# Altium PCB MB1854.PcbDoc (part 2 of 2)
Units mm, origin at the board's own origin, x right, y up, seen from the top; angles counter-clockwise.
Board outline 50.11 x 30.1 mm, 4 copper layers (Top Layer, Signal Layer 1, Signal Layer 2, Bottom Layer), stack 1.556 mm thick; 50 components, 31 nets, 194 pads, 158 vias.
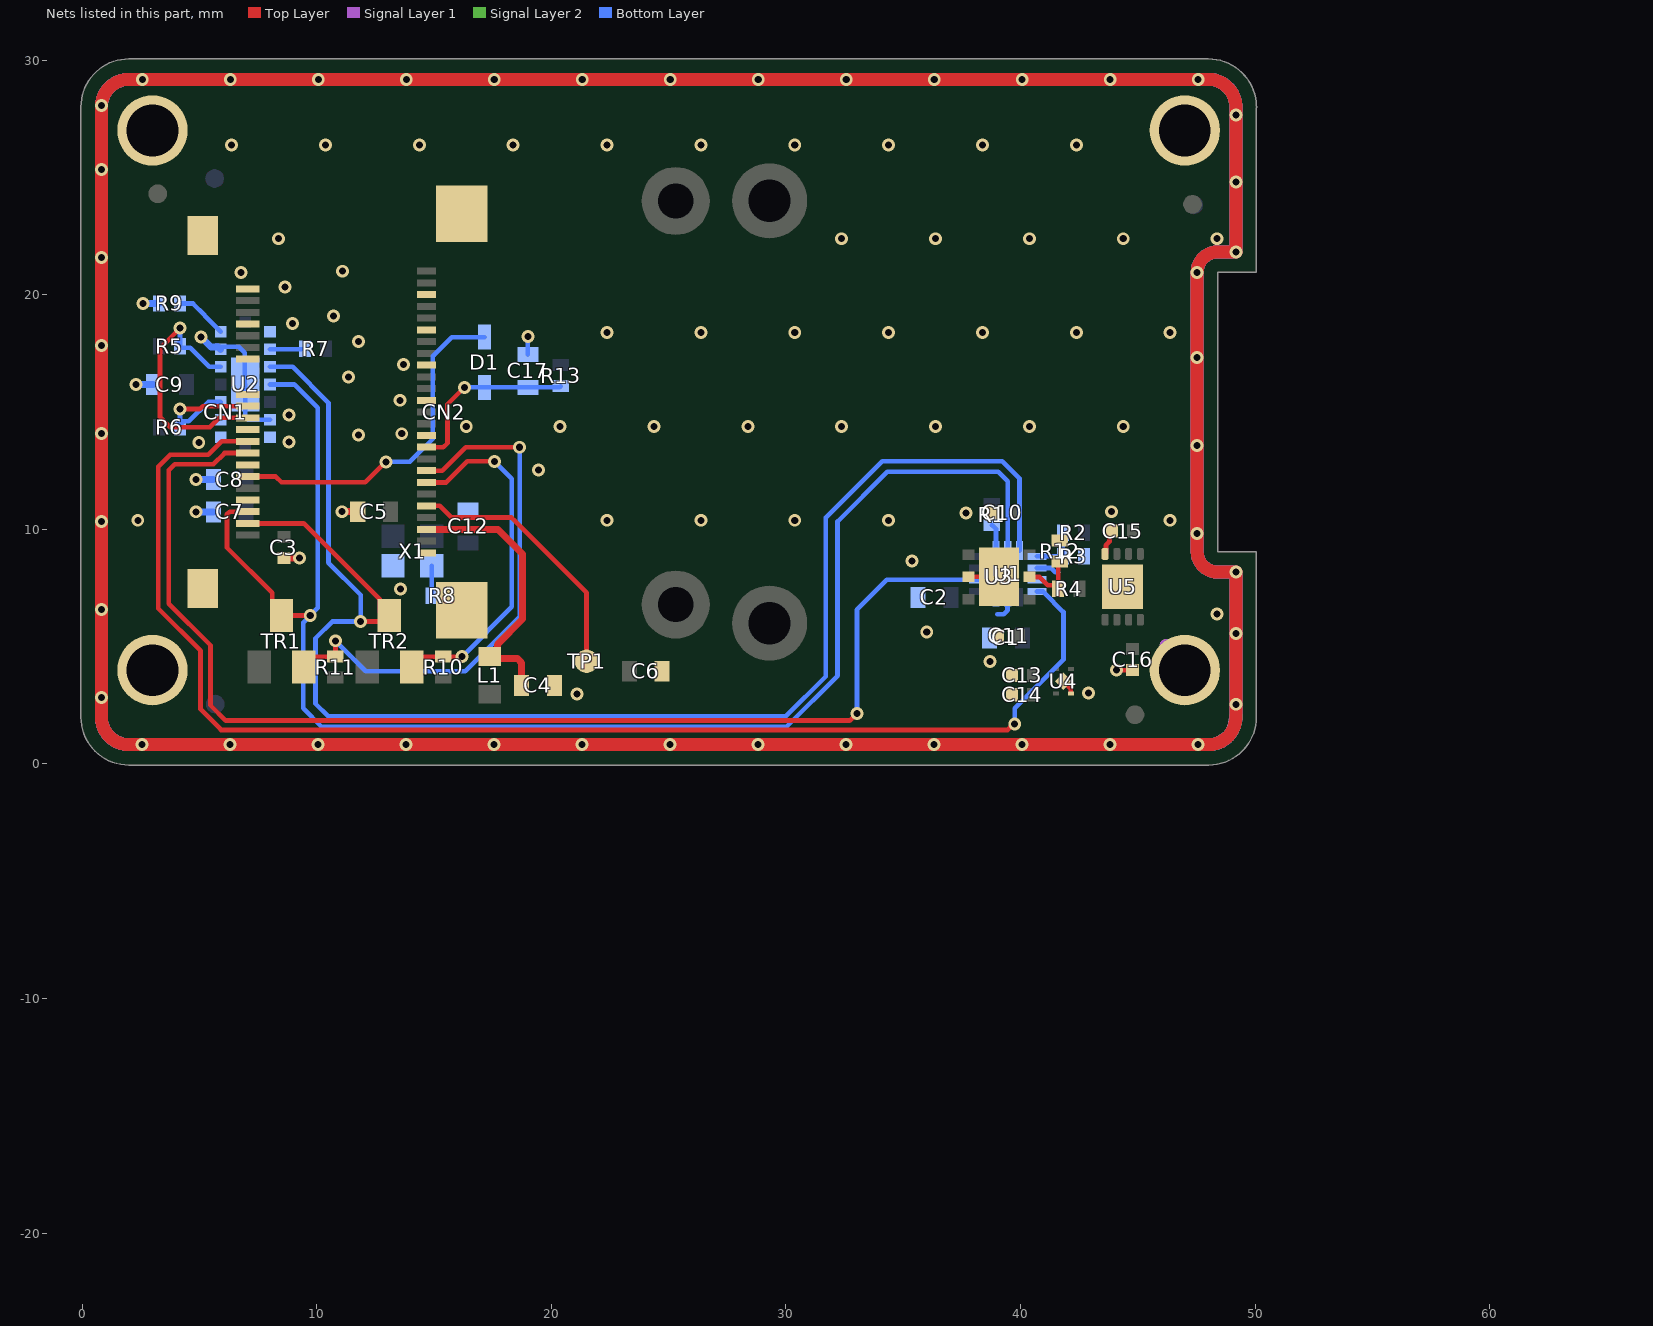
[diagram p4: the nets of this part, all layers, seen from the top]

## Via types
v1: diameter 0.55, hole 0.3, Top Layer to Bottom Layer, tented both sides, 158 vias

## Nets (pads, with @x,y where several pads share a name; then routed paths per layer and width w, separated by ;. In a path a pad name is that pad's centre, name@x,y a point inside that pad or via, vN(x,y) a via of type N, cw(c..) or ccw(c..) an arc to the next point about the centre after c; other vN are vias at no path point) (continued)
GND: C1.1 C2.1 C3.1 C4.2 C5.2 C6.2 C7.1 C8.1 C9.1 C10.1 C11.1 C12.1 C13.1 C14.1 C15.1 C16.1 C17.2 CN1.1 CN1.4 CN1.7 CN1.10 CN1.13 CN1.16 CN1.19 CN1.S1 CN1.S2 CN2.1 CN2.11 CN2.14 CN2.17 CN2.20 CN2.23 CN2.S1 CN2.S2 pad.1@3,4 pad.1@3,27 pad.1@47,4 pad.1@47,27 R3.1 R9.1 R12.1 U1.2 U1.3 U1.6 U1.7 U2.A2 U2.A6 U2.A7 U2.B4 U2.C1 U2.C6 U2.C7 U3.2 U3.EP U4.2 U4.5 U5.4 U5.9 X1.2 | length 635.1
  Top Layer w0.2: U3.2@37.778,7.975 U3.EP@39.078,7.975 ; U4.5@41.828,3.525 42.142,3.21 U4.2@42.142,3.05 ; U5.4@43.603,8.95 43.638,8.985 43.638,9.326 43.789,9.477 43.789,9.814 C15.1@43.9,9.925 ; v1(44.088,4) C16.1@44.763,4
  Top Layer w0.3: C3.1@8.6,8.775 v1@9.225,8.775 ; v1(11.075,10.75) C5.2@11.75,10.75
  Top Layer w0.55: v1(0.825,28.071) 0.825,25.342 0.825,21.592 0.825,17.842 v1(0.826,14.091) v1(0.826,10.341) v1(0.826,6.591) 0.826,3.667 v1(0.826,2.841) 0.827,2.014 cw(c-0.048,2.014) 0.825,1.968 ccw(c1.375,1.94) 0.825,1.939 ccw(c1.375,1.938) 0.835,1.831 0.859,1.71 ccw(c1.399,1.818) 0.89,1.607 0.938,1.493 ccw(c1.446,1.704) 0.988,1.398 1.057,1.296 ccw(c1.514,1.601) 1.124,1.214 1.212,1.125 ccw(c1.601,1.514) 1.296,1.057 1.443,0.959 1.607,0.891 ccw(c1.817,1.399) 1.709,0.86 1.831,0.835 ccw(c1.938,1.375) 1.938,0.825 v1(2.558,0.825) v1(6.308,0.825) v1(10.058,0.825) v1(13.809,0.825) v1(17.559,0.825) v1(21.309,0.825) v1(25.06,0.825) v1(28.81,0.825) v1(32.56,0.825) v1(36.31,0.825) v1(40.061,0.825) v1(43.811,0.825) v1(47.561,0.825) 48.014,0.825 ccw(c48.014,1.375) 48.02,0.825 48.074,0.825 ccw(c48.068,1.375) 48.18,0.837 48.301,0.862 ccw(c48.188,1.4) 48.403,0.894 48.515,0.942 ccw(c48.3,1.448) 48.609,0.993 48.71,1.061 ccw(c48.402,1.517) 48.792,1.13 48.879,1.217 ccw(c48.488,1.604) 48.947,1.301 49.014,1.402 ccw(c48.555,1.706) 49.064,1.496 49.11,1.609 ; v1@0.827,28.071 cw(c1.377,28.071) 0.837,28.179 0.859,28.29 cw(c1.399,28.182) 0.89,28.393 0.938,28.507 cw(c1.446,28.296) 0.988,28.602 1.057,28.705 cw(c1.514,28.399) 1.125,28.788 1.212,28.874 cw(c1.601,28.486) 1.296,28.943 1.399,29.012 cw(c1.704,28.554) 1.494,29.063 1.607,29.109 cw(c1.818,28.601) 1.711,29.141 1.832,29.165 cw(c1.938,28.625) 1.938,29.175 v1(2.567,29.175) v1(6.318,29.175) v1(10.068,29.175) v1(13.818,29.175) v1(17.568,29.175) v1(21.319,29.175) v1(25.069,29.175) v1(28.819,29.175) v1(32.57,29.175) v1(36.32,29.175) v1(40.07,29.175) v1(43.82,29.175) v1(47.571,29.175) 47.737,29.175 48,29.175 48.061,29.175 cw(c48.061,28.625) 48.168,29.165 48.286,29.142 cw(c48.181,28.602) 48.389,29.111 48.5,29.065 cw(c48.293,28.556) 48.597,29.014 48.697,28.948 cw(c48.395,28.489) 48.782,28.88 48.867,28.796 cw(c48.482,28.403) 48.937,28.712 49.004,28.614 cw(c48.551,28.302) 49.057,28.518 49.104,28.409 cw(c48.599,28.19) 49.137,28.305 49.162,28.187 cw(c48.624,28.071) 49.174,28.079 49.175,28.019 ccw(c50.05,28.034) 49.177,27.98 cw(c48.628,27.946) 49.178,27.944 v1(49.178,27.661) 49.178,27.378 v1(49.175,24.8) v1(49.176,21.825) 48.4,21.825 ccw(c48.4,20.95) v1(47.525,20.95) v1(47.525,17.322) v1(47.525,13.571) v1(47.525,9.821) 47.525,9.05 ccw(c48.4,9.05) 48.4,8.175 v1(49.175,8.175) v1(49.175,5.562) v1(49.175,2.543) 49.175,1.92 ; 49.11,1.609 ccw(c48.602,1.819) 49.142,1.714 49.165,1.831 ccw(c48.626,1.941) 49.175,1.919
  Signal Layer 1 w0.55: pad.1@46.193,3.16 pad.1@46.193,5.046 ; 49.175,26.922 49.175,28.049 49.174,28.079 ccw(c48.624,28.071) 49.162,28.188 49.137,28.305 ccw(c48.599,28.19) 49.104,28.409 49.057,28.518 ccw(c48.551,28.302) 49.004,28.614 48.937,28.712 ccw(c48.482,28.403) 48.867,28.796 48.782,28.88 ccw(c48.395,28.489) 48.697,28.948 48.597,29.014 ccw(c48.293,28.556) 48.501,29.065 48.39,29.111 ccw(c48.181,28.602) 48.285,29.142 48.169,29.165 ccw(c48.062,28.625) 48.077,29.175 ccw(c48.048,28.049) 48.048,29.175 v1(47.571,29.175) v1(43.82,29.175) v1(40.07,29.175) v1(36.32,29.175) v1(32.57,29.175) v1(28.819,29.175) v1(25.069,29.175) v1(21.319,29.175) v1(17.568,29.175) v1(13.818,29.175) v1(10.068,29.175) v1(6.318,29.175) v1(2.567,29.175) 1.938,29.175 ccw(c1.938,28.625) 1.832,29.165 1.711,29.141 ccw(c1.818,28.601) 1.607,29.109 1.494,29.063 ccw(c1.704,28.554) 1.398,29.011 1.267,28.924 ccw(c1.571,28.466) 1.265,28.923 1.251,28.913 1.125,28.788 ccw(c1.514,28.399) 1.057,28.705 0.988,28.602 ccw(c1.446,28.296) 0.938,28.507 0.89,28.393 ccw(c1.399,28.182) 0.859,28.29 0.837,28.178 ccw(c1.376,28.071) 0.826,28.071 v1(0.826,25.342) v1(0.826,21.592) v1(0.826,17.842) v1(0.826,14.091) v1(0.826,10.341) v1(0.826,6.591) v1(0.826,2.841) 0.827,2.014 cw(c-0.048,2.014) 0.825,1.968 ccw(c1.375,1.94) 0.825,1.94 0.825,1.884 0.859,1.71 ccw(c1.399,1.818) 0.89,1.607 0.938,1.493 ccw(c1.446,1.704) 0.988,1.398 1.057,1.296 ccw(c1.514,1.601) 1.125,1.213 1.212,1.125 ccw(c1.601,1.514) 1.296,1.057 1.398,0.989 ccw(c1.704,1.446) 1.493,0.938 1.607,0.891 ccw(c1.817,1.399) 1.709,0.86 1.831,0.835 ccw(c1.938,1.375) 1.938,0.825 v1(2.558,0.825) 3.496,0.825 48.016,0.825 ccw(c48.014,1.375) 48.02,0.825 48.074,0.825 ccw(c48.068,1.375) 48.18,0.837 48.301,0.862 ccw(c48.188,1.4) 48.403,0.894 48.515,0.942 ccw(c48.3,1.448) 48.609,0.993 48.71,1.061 ccw(c48.402,1.517) 48.792,1.13 48.879,1.217 ccw(c48.488,1.604) 48.946,1.3 48.984,1.357 ccw(c48.526,1.661) 49.043,1.473 ccw(c46.944,2.231) 49.175,2.231 v1(49.175,2.543) v1(49.175,5.562) v1(49.175,8.175) 48.4,8.175 cw(c48.4,9.05) 47.525,9.05 v1(47.525,9.821) v1(47.525,13.571) v1(47.525,17.322) v1(47.525,20.95) cw(c48.4,20.95) 48.4,21.825 v1(49.176,21.825) 49.176,26.922
  Signal Layer 2 w0.55: 0.825,1.968 ccw(c1.969,1.968) 0.828,1.894 ccw(c1.377,1.928) 0.837,1.82 0.859,1.709 ccw(c1.399,1.818) 0.89,1.607 0.938,1.493 ccw(c1.446,1.704) 0.988,1.398 1.057,1.296 ccw(c1.514,1.601) 1.125,1.213 1.212,1.125 ccw(c1.601,1.514) 1.296,1.057 1.398,0.989 ccw(c1.704,1.446) 1.493,0.938 1.607,0.891 ccw(c1.817,1.399) 1.71,0.859 1.824,0.836 ccw(c1.932,1.376) 1.895,0.827 ccw(c1.969,1.968) 1.969,0.825 v1(2.558,0.825) v1(6.308,0.825) v1(10.058,0.825) v1(13.809,0.825) v1(17.559,0.825) v1(21.309,0.825) v1(25.06,0.825) v1(28.81,0.825) v1(32.56,0.825) v1(36.31,0.825) v1(40.061,0.825) v1(43.811,0.825) v1(47.561,0.825) 48.014,0.825 ccw(c48.014,1.375) 48.02,0.825 48.074,0.825 ccw(c48.068,1.375) 48.18,0.837 48.301,0.862 ccw(c48.188,1.4) 48.403,0.894 48.515,0.942 ccw(c48.3,1.448) 48.609,0.993 48.71,1.061 ccw(c48.402,1.517) 48.792,1.13 48.879,1.217 ccw(c48.488,1.604) 48.946,1.3 48.985,1.359 49.014,1.402 ccw(c48.555,1.706) 49.064,1.497 49.11,1.609 ccw(c48.602,1.819) 49.141,1.712 49.165,1.831 ccw(c48.625,1.939) 49.175,1.939 v1(49.175,2.543) v1(49.175,5.562) v1(49.175,8.175) 48.4,8.175 cw(c48.4,9.05) 47.525,9.05 v1(47.525,9.821) v1(47.525,13.571) v1(47.525,17.322) v1(47.525,20.95) cw(c48.4,20.95) 48.4,21.825 v1(49.176,21.825) v1(49.175,24.8) 49.177,26.089 49.177,27.956 ccw(c48.627,27.957) 49.176,27.987 cw(c50.05,28.034) 49.175,28.019 49.174,28.079 ccw(c48.624,28.071) 49.162,28.187 49.137,28.305 ccw(c48.599,28.19) 49.104,28.409 49.057,28.518 ccw(c48.551,28.302) 49.004,28.614 48.921,28.735 ; 0.826,1.968 0.826,2 cw(c1.376,2.001) 0.826,2.006 ccw(c-0.048,2.014) 0.827,2.014 v1(0.826,2.841) 0.826,2.869 v1(0.826,6.591) v1(0.826,10.341) v1(0.826,14.091) v1(0.826,17.842) v1(0.826,21.592) v1(0.826,25.342) 0.826,28.071 cw(c1.376,28.071) 0.837,28.178 0.859,28.29 cw(c1.399,28.182) 0.89,28.393 0.938,28.507 cw(c1.446,28.296) 0.988,28.602 1.023,28.653 1.057,28.704 cw(c1.514,28.399) 1.125,28.788 1.212,28.874 cw(c1.601,28.486) 1.296,28.943 1.399,29.012 cw(c1.704,28.554) 1.494,29.063 1.607,29.109 cw(c1.818,28.601) 1.711,29.141 1.832,29.165 cw(c1.938,28.625) 1.938,29.175 v1(2.567,29.175) v1(6.318,29.175) v1(10.068,29.175) v1(13.818,29.175) v1(17.568,29.175) v1(21.319,29.175) v1(25.069,29.175) v1(28.819,29.175) v1(32.57,29.175) v1(36.32,29.175) v1(40.07,29.175) v1(43.82,29.175) v1(47.571,29.175) 48.061,29.175 cw(c48.061,28.625) 48.168,29.165 48.286,29.142 cw(c48.181,28.602) 48.389,29.111 48.5,29.065 cw(c48.293,28.556) 48.597,29.014 48.697,28.948 cw(c48.395,28.489) 48.782,28.88 48.87,28.793 cw(c48.485,28.4) 48.921,28.736
  Bottom Layer w0.2: U2.A2@5.808,17.775 6.675,17.775 6.934,17.516 6.934,16.198 U2.B4@6.958,16.175 6.958,14.792 7.075,14.675 U2.C6@8.008,14.675 ; C17.2@19,17.45 v1(19,18.225) ; 39.007,6.382 39.282,6.382 39.446,6.546 39.446,7.093 U1.6@39.459,7.107 ; U1.2@40.703,8.35 41.3,8.35 41.475,8.175 41.6,8.175
  Bottom Layer w0.3: v1@2.303,16.173 2.308,16.168 C9.1@3.045,16.168 ; v1(2.6,19.625) R9.1@3.275,19.625 ; v1@4.85,10.75 4.855,10.745 C7.1@5.592,10.745 ; v1@4.853,12.125 4.858,12.12 C8.1@5.595,12.12 ; v1(5.075,18.2) 5.5,17.775 5.808,17.775 U2.A2@5.908,17.675
  Bottom Layer w0.55: v1(6.308,0.825) 5.656,0.825 ; 5.656,0.825 45.276,0.825 v1(47.561,0.825) 48.016,0.825 ccw(c48.014,1.375) 48.02,0.825 48.074,0.825 ccw(c48.068,1.375) 48.179,0.837 48.301,0.862 ccw(c48.188,1.4) 48.402,0.894 48.564,0.963 48.709,1.061 ccw(c48.402,1.517) 48.792,1.13 48.879,1.217 ccw(c48.488,1.604) 48.947,1.301 49.014,1.402 ccw(c48.555,1.706) 49.064,1.497 49.11,1.609 ccw(c48.602,1.819) 49.141,1.712 49.165,1.831 ccw(c48.625,1.939) 49.175,1.939 v1(49.175,2.543) v1(49.175,5.562) v1(49.175,8.175) 48.4,8.175 cw(c48.4,9.05) 47.782,8.432 cw(c48.4,9.05) 47.525,9.05 v1(47.525,9.821) v1(47.525,13.571) v1(47.525,17.322) v1(47.525,20.95) cw(c48.4,20.95) 48.4,21.825 v1(49.176,21.825) v1(49.175,24.8) 49.177,26.479 v1(49.178,27.661) 49.178,27.944 ccw(c48.628,27.946) 49.177,27.98 cw(c50.05,28.034) 49.175,28.019 49.174,28.079 ccw(c48.624,28.071) 49.162,28.187 49.137,28.305 ccw(c48.599,28.19) 49.104,28.409 49.057,28.518 ccw(c48.551,28.302) 49.004,28.614 48.921,28.735 48.92,28.737 48.913,28.746 ccw(c48.485,28.4) 48.87,28.793 48.782,28.88 ccw(c48.395,28.489) 48.697,28.948 48.597,29.014 ccw(c48.293,28.556) 48.5,29.065 48.389,29.111 ccw(c48.181,28.602) 48.286,29.142 48.168,29.165 ccw(c48.061,28.625) 48.061,29.175 v1(47.571,29.175) v1(43.82,29.175) v1(40.07,29.175) v1(36.32,29.175) v1(32.57,29.175) v1(28.819,29.175) v1(25.069,29.175) v1(21.319,29.175) v1(17.568,29.175) v1(13.818,29.175) v1(10.068,29.175) v1(6.318,29.175) v1(2.567,29.175) 1.938,29.175 ccw(c1.938,28.625) 1.832,29.165 1.711,29.141 ccw(c1.818,28.601) 1.607,29.109 1.494,29.063 ccw(c1.704,28.554) 1.398,29.011 1.267,28.924 ccw(c1.571,28.466) 1.265,28.923 1.251,28.913 1.125,28.788 ccw(c1.514,28.399) 1.057,28.705 0.988,28.602 ccw(c1.446,28.296) 0.938,28.507 0.89,28.393 ccw(c1.399,28.182) 0.859,28.29 0.835,28.17 ccw(c1.375,28.062) 0.825,28.062 0.825,25.629 0.825,25.342 0.825,21.592 0.825,17.842 v1(0.826,14.091) v1(0.826,10.341) v1(0.826,6.591) 0.826,4.601 v1(0.826,2.841) 0.827,2.014 cw(c-0.048,2.014) 0.825,1.968 ccw(c1.375,1.94) 0.825,1.939 ccw(c1.375,1.938) 0.835,1.832 0.859,1.71 ccw(c1.399,1.818) 0.89,1.607 0.914,1.55 0.938,1.492 ccw(c1.446,1.704) 0.988,1.398 1.057,1.296 ccw(c1.514,1.601) 1.125,1.213 1.212,1.125 ccw(c1.601,1.514) 1.296,1.057 1.398,0.989 ccw(c1.704,1.446) 1.493,0.938 1.607,0.891 ccw(c1.817,1.399) 1.709,0.86 1.831,0.835 ccw(c1.938,1.375) 1.938,0.825 v1(2.558,0.825) 5.656,0.825
  other v1: 21.1,2.975 42.9,3.025 38.7,4.375 36,5.625 48.375,6.385 13.575,7.45 35.375,8.65 9.275,8.775 2.375,10.385 22.375,10.385 26.375,10.385 30.375,10.385 34.375,10.385 46.375,10.385 37.675,10.7 4.852,10.748 43.875,10.75 4.855,12.123 19.45,12.525 4.975,13.7 8.825,13.725 11.775,14.025 13.625,14.075 16.375,14.385 20.375,14.385 24.375,14.385 28.375,14.385 32.375,14.385 36.375,14.385 40.375,14.385 44.375,14.385 8.825,14.875 13.55,15.5 2.305,16.17 11.35,16.5 13.7,17.025 11.775,18 22.375,18.385 26.375,18.385 30.375,18.385 34.375,18.385 38.375,18.385 42.375,18.385 46.375,18.385 8.975,18.775 10.725,19.1 8.65,20.325 6.775,20.95 11.1,21 8.375,22.385 32.375,22.385 36.375,22.385 40.375,22.385 44.375,22.385 48.375,22.385 6.375,26.385 10.375,26.385 14.375,26.385 18.375,26.385 22.375,26.385 26.375,26.385 30.375,26.385 34.375,26.385 38.375,26.385 42.375,26.385
I2C_SCL: CN1.20 TR1.3 U1.13 U2.C4 | length 65.8
  Top Layer w0.2: CN1.20@7.053,10.75 6.292,10.75 6.175,10.633 6.175,9.225 8.1,7.3 8.1,6.725 TR1.3@8.5,6.325 TR1.3@8.669,6.325 ; TR1.3@8.669,5.719 TR1.3@8.669,6.325 ; TR1.3@8.669,6.781 TR1.3@8.669,6.325 ; v1(9.725,6.325) TR1.3@8.669,6.325
  Bottom Layer w0.2: U2.C4@8.008,16.175 9.05,16.175 10.05,15.175 10.05,6.65 v1(9.725,6.325) 9.425,6.025 9.425,2.375 10.225,1.575 30.015,1.575 32.2,3.76 32.2,10.333 34.317,12.45 37.15,12.45 39.05,12.45 39.453,12.047 U1.13@39.453,9.1
I2C_SCL_1V8: CN2.8 R11.1 TR1.2 | length 23.1
  Top Layer w0.2: TR1.2@9.45,4.125 9.45,4.175 9.85,4.575 R11.1@10.8,4.575 ; R11.1@10.797,4.678 R11.1@10.8,4.675 ; R11.1@10.799,4.576 10.8,4.578 R11.1@10.8,4.675 ; R11.1@10.799,4.678 R11.1@10.8,4.679 ; v1(10.8,5.25) R11.1@10.8,4.679 ; CN2.8@14.675,12.5 14.678,12.497 15.347,12.497 16.347,13.497 v1(18.649,13.497) ; R11.1@10.8,4.675 R11.1@10.8,4.679
  Bottom Layer w0.2: v1(10.8,5.25) 12.1,3.95 16.325,3.95 18.649,6.274 v1@18.649,13.374
I2C_SDA: CN1.21 TR2.3 U1.14 U2.C3 | length 69.2
  Top Layer w0.2: CN1.21@7.053,10.25 9.45,10.25 12.7,7 12.7,6.475 TR2.3@12.85,6.325 ; v1(11.875,6.075) 12.85,6.075 TR2.3@13.1,6.325
  Bottom Layer w0.2: U2.C3@8.008,16.925 8.975,16.925 10.5,15.4 10.5,8.575 11.875,7.2 v1(11.875,6.075) 10.675,6.075 9.95,5.35 9.95,2.575 10.5,2.025 29.998,2.025 31.7,3.727 31.7,10.5 34.1,12.9 37.425,12.9 39.225,12.9 39.953,12.172 U1.14@39.953,9.1
I2C_SDA_1V8: CN2.7 R10.1 TR2.2 | length 15.2
  Top Layer w0.2: TR2.2@13.778,4.175 14.178,4.575 R10.1@15.228,4.575 ; CN2.7@14.675,12 14.678,11.997 15.522,11.997 16.422,12.897 v1(17.574,12.897) ; R10.1@15.4,4.575 v1(16.2,4.575)
  Bottom Layer w0.2: v1(16.2,4.575) 18.319,6.694 18.319,12.152 v1(17.574,12.897)
IMU_INT1: CN1.14 U1.4 | length 57.6
  Top Layer w0.2: CN1.14@7.053,13.75 5.95,13.75 5.375,13.175 3.75,13.175 3.25,12.675 3.25,6.625 5.05,4.825 5.05,2.325 5.925,1.45 39.458,1.45 39.708,1.7 v1(39.75,1.7)
  Bottom Layer w0.2: v1(39.75,1.7) 39.75,2.375 41.825,4.45 41.825,6.475 41.003,7.297 41.003,7.3 40.953,7.35 U1.4@40.703,7.35
IMU_INT2: CN1.15 U1.9 | length 52.5
  Top Layer w0.2: CN1.15@7.053,13.25 6.075,13.25 5.6,12.775 3.95,12.775 3.7,12.525 3.7,6.825 5.475,5.05 5.475,2.5 6.125,1.85 32.725,1.85 v1(33.025,2.15)
  Bottom Layer w0.2: v1(33.025,2.15) 33.025,6.575 34.3,7.85 U1.9@38.203,7.85
NetC4_1: C4.1 CN2.3 L1.2 | length 12
  Top Layer w0.3: CN2.3@14.675,10 17.725,10 18.775,8.95 18.775,6.175 17.7,5.1 17.7,4.825 17.45,4.575 L1.2@17.375,4.575 17.464,4.486 18.552,4.486 18.728,4.311 C4.1@18.728,3.35
NetCN2_5: CN2.5 TP1.1 | length 11
  Top Layer w0.2: CN2.5@14.675,11 15.25,11 15.75,10.5 18.303,10.5 18.457,10.346 21.503,7.3 TP1.1@21.503,4.65
NetR1_1: R1.1 U1.12 | length 1.2
  Bottom Layer w0.2: R1.1@38.775,10.175 38.798,10.175 38.953,10.02 U1.12@38.953,9.1
NetR2_1: R2.1 R3.2 U1.1 | length 2.1
  Bottom Layer w0.2: U1.1@40.703,8.85 R3.2@41.803,8.85 R2.1@41.803,9.85
NetR4_1: R4.1 R12.2 U3.5 | length 2.6
  Top Layer w0.2: U3.5@40.378,7.975 40.388,7.965 40.81,7.965 41.165,7.61 41.467,7.61 R4.1@41.603,7.475 41.603,8.55 R12.2@41.678,8.625
NetR7_1: R7.1 U2.C2 | length 1.5
  Bottom Layer w0.2: U2.C2@8.008,17.675 9.475,17.675 R7.1@9.5,17.7
NetR8_2: R8.2 X1.1 | length 1.3
  Bottom Layer w0.2: R8.2@14.9,7.175 14.903,7.178 X1.1@14.903,8.45
NetR9_2: R9.2 U2.A1 | length 2.2
  Bottom Layer w0.2: R9.2@4.175,19.625 4.725,19.625 5.225,19.125 5.225,19.108 U2.A1@5.908,18.425
NRST_CAM: CN1.17 D1.2 | length 14.8
  Top Layer w0.2: CN1.17@7.053,12.25 8.25,12.25 8.5,12 12.075,12 v1(12.95,12.875)
  Bottom Layer w0.2: v1(12.95,12.875) 13.975,12.875 14.95,13.85 14.95,17.375 15.765,18.19 D1.2@17.15,18.19
RESET: C17.1 CN2.10 D1.1 R13.2 | length 7.8
  Top Layer w0.2: CN2.10@14.675,13.5 15.4,13.5 15.575,13.675 15.575,15.325 v1(16.3,16.05)
  Bottom Layer w0.2: v1(16.3,16.05) D1.1@17.15,16.05 C17.1@19,16.05 20.35,16.05 R13.2@20.4,16.1
TOF_INT: CN1.12 R5.1 U2.A3 | length 11.1
  Top Layer w0.2: v1(4.175,18.575) 3.325,17.725 3.325,14.775 3.75,14.35 5.45,14.35 5.85,14.75 CN1.12@7.053,14.75
  Bottom Layer w0.2: v1(4.175,18.575) R5.1@4.175,17.8 4.238,17.737 4.613,17.737 5.425,16.925 U2.A3@5.908,16.925
TOF_LPn: CN1.11 R6.1 U2.A5 | length 5.9
  Top Layer w0.2: v1(4.175,15.125) 5.017,15.125 5.142,15.25 CN1.11@7.053,15.25
  Bottom Layer w0.2: v1(4.175,15.125) R6.1@4.175,14.35 4.175,14.445 4.33,14.6 4.55,14.6 5.375,15.425 U2.A5@5.908,15.425
pads on no net: CAM.1 CN2.9 CN2.21 CN2.22 CN2.24 CN2.25 MIRE24.1 MIRE25.1 MIRE26.1 MIRE27.1 MIRE28.1 MIRE29.1 U1.10 U1.11 U2.C5 U3.3 U5.3 U5.6 U5.7

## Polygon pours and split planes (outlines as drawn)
GND on Top Layer "GND" (solid, remove dead copper, pour order 20): -0.447,8.775 -0.447,28.425 0.753,29.625 49.053,29.625 50.003,28.675 50.003,0.725 48.328,-0.95 2.901,-0.95 -0.447,2.399
2V8 on Top Layer "2V8" (solid, remove dead copper, pour order 12): 39.775,5.075 39.875,4.975 41.1,4.975 43.15,7.025 43.15,7.4 43.3,7.55 44.075,7.55 44.15,7.625 44.15,8.95 43.975,9.125 43.225,9.125 43.125,9.025 43.125,8.4 42.95,8.225 42.275,8.225 42.05,8 42.05,7.225 41.8,6.975 41.325,6.975 40.9,7.4 40.2,7.4 40.05,7.25 40.05,6.675 39.775,6.4
3V3 on Top Layer "3V3" (solid, remove dead copper, pour order 19): 41.425,4.85 41.65,4.625 41.65,3.925 41.225,3.5 40.2,3.5 40.025,3.675 40.025,4.7 40.175,4.85
1V2 on Top Layer "1V2" (solid, remove dead copper, pour order 14): 42.9,3.725 43.125,3.95 43.125,4.75 42.95,4.925 42.5,4.925 41.975,4.4 41.975,3.95 42.2,3.725
1V8 on Top Layer "1V8" (solid, remove dead copper, pour order 13): 41.675,3.125 41.35,3.45 40.3,3.45 40.15,3.3 40.15,2.375 40.625,1.9 41.4,1.9 41.675,2.175
3V3 on Signal Layer 2 "3V3" (solid, remove dead copper, pour order 18): -0.575,10.785 -0.575,29.435 1.625,31.635 49.368,31.635 51.028,29.975 51.028,2.7 47.378,-0.95 2.685,-0.95 -0.575,2.31
1V2 on Signal Layer 2 "1V2" (solid, remove dead copper, pour order 15): 44.25,5.2 44.45,5 44.45,4.363 42.888,2.8 31.775,2.8 31.5,2.525 22.825,2.525 22.825,3.175 23.05,3.4 31.15,3.4 32.025,4.275 41.3,4.275 41.375,4.35 42.28,5.2
2V8 on Signal Layer 2 "2V8" (solid, remove dead copper, pour order 16): 39.55,4.475 40.175,5.1 41.175,5.1 41.475,5.4 41.475,5.775 41.225,6.025 39.43,6.025 38.825,5.4 31.5,5.4 30.552,4.452 16.727,4.452 15.9,3.625 15.9,2.8 16.175,2.525 22.575,2.525 22.65,2.6 22.65,3.225 23,3.575 31.075,3.575 31.975,4.475
1V8 on Signal Layer 2 "1V8" (solid, remove dead copper, pour order 5): 17.825,9.025 17.825,13.175 21.2,16.55 21.2,17.975 20.775,18.4 19.2,18.4 12.675,11.875 12.675,4.275 12,3.6 7.275,3.6 6.875,3.2 6.875,1.225 43.65,1.225 45.375,2.95 45.375,6.55 42.55,9.375 36.8,9.375 36.55,9.125 36.55,8.7 36.75,8.5 42.425,8.5 44.625,6.3 44.625,4.25 43,2.625 31.857,2.625 31.6,2.375 16,2.375 15.75,2.625 15.75,3.775 17.825,5.85
GND on Signal Layer 1 "GND" (solid, remove dead copper, pour order 10): -0.575,10.785 -0.575,29.435 1.625,31.635 47.693,31.635 50.128,29.2 50.128,1.449 47.729,-0.95 2.376,-0.95 -0.575,2.001
GND on Bottom Layer "GND" (solid, remove dead copper, pour order 11): -0.575,10.785 -0.575,29.435 1.625,31.635 49.368,31.635 51.028,29.975 51.028,2.7 47.378,-0.95 2.685,-0.95 -0.575,2.31

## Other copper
Top Layer:
  text "1" at 5.621,27.55 h1.5
  text ".Layer_Name" at 4.398,-14.913 h3
  text ".GTL" at 46.093,-14.913 h3
Signal Layer 1:
  text "2" at 6.644,27.55 h1.5
  text ".Layer_Name" at 4.391,-14.905 h3
  text ".G1" at 46.086,-14.905 h3
Signal Layer 2:
  text "3" at 8.225,27.56 h1.5
  text ".Layer_Name" at 4.391,-14.905 h3
  text ".G2" at 46.086,-14.905 h3
Bottom Layer:
  text "4" at 9.275,27.56 h1.5
  text ".GBL" at 34.882,-14.937 h3
  text ".Layer_Name" at 76.196,-14.937 h3
Multi-Layer:
  pour cut-out: 5.408,28.713 9.586,28.713 9.586,27.337 5.408,27.337

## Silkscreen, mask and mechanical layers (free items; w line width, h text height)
Top Overlay:
  lines w0.12: 21.968,11.95 23.768,11.95 47.303,11.95 ; 21.968,18.05 23.768,18.05 47.283,18.05
  text "H" at 32.778,24.925 h7
  text "E" at 38.607,24.426 h8
  text "I" at 36.15,20.316 h5.5
  text "G" at 43.128,20.158 h4.5
Bottom Overlay:
  text "J" at 37.753,20.611 h12 r270
  text "MB1854B" at 36.475,20.2 h2 r270
  text "AI  / Camera module" at 43.603,19.75 h1.5 r270
Top Paste:
  text ".Layer_Name" at 4.398,-14.913 h3
  text ".GTP" at 46.093,-14.913 h3
Bottom Paste:
  text ".GBP" at 34.882,-14.937 h3
  text ".Layer_Name" at 76.196,-14.937 h3
Top Solder:
  pour cut-out: 9.586,27.337 5.408,27.337 5.408,28.713 9.586,28.713
  text ".Layer_Name" at 4.398,-14.913 h3
  text ".GTS" at 46.093,-14.913 h3
Bottom Solder:
  pour cut-out: 9.573,27.337 5.394,27.337 5.394,28.713 9.573,28.713
  text ".GBS" at 34.882,-14.937 h3
  text ".Layer_Name" at 76.196,-14.937 h3
M1-Board Shape:
  lines w0.1: 0,2 ccw(c2,2) 2,0 48.018,0 ccw(c48,2) 50,2 50,9 48.35,9 48.35,21 50,21 50,28 ccw(c48,28) 48,30 2,30 ccw(c2,28) 0,28 0.003,2
  lines w0.12: 50,28 50,28
M2-Board Dimensions:
  text ".Layer_Name" at 4.398,-14.913 h3
  text ".GM2" at 46.093,-14.913 h3
M14-Top Assembly:
  lines w0.01: 21.388,11.675 cw(c21.663,11.675) 21.663,11.95 23.463,11.95 49.75,11.95 49.75,18.05 23.463,18.05 21.663,18.05 cw(c21.663,18.325) 21.388,18.325 ; 16.788,8.45 16.788,21.55 21.388,21.55 21.388,8.45 16.788,8.45
  text ".Layer_Name" at 4.398,-14.913 h3
  text ".GM14" at 46.093,-14.913 h3
M15-Bottom Assembly:
  lines w0.01: 49.75,11.95 49.75,18.05
  text ".GM15" at 34.882,-14.937 h3
  text ".Layer_Name" at 76.196,-14.937 h3
M16-Top Courtyard:
  lines w0.01: 24.025,11.7 50,11.7 50,18.3 24,18.3 22.2,18.3 cw(c22.2,18.85) 21.65,18.85 21.65,21.8 16.55,21.8 16.55,8.2 21.65,8.2 21.65,11.125 cw(c22.225,11.125) 22.225,11.7 24.054,11.7
Drill Drawing:
  drawing of 329 lines, arcs and shapes, not listed
  text "PCB SPECIFICATIONS :" at -1.527,82.512 h3
  text "MINIMUN PARAMETERS" at 155.773,79.187 h3
  text "A.   MATERIAL :" at -1.527,78.512 h3
  text "FR-4" at 36.973,78.512 h3
  text "TG-170" at 53.473,78.512 h3
  text "X  TG-150" at 71.723,78.512 h3
  text "TG-140" at 87.723,78.512 h3
  text "B.   MATERIAL FAMILY :" at -1.527,75.512 h3
  text "N/A" at 36.973,75.512 h3
  text "DEFAULT" at 155.773,73.687 h3
  text "C.   SOLDERMASK COLOR :" at -1.527,72.512 h3
  text "GREEN" at 36.973,72.512 h3
  text "BLACK" at 53.473,72.512 h3
  text "RED" at 71.723,72.512 h3
  text "X  Blue ink PANTONE 2955" at 87.723,72.512 h3
  text "D.   SILKSCREEN COLOR :" at -1.527,69.512 h3
  text "X  WHITE" at 36.973,69.512 h3
  text "YELLOW" at 53.473,69.512 h3
  text "BLACK" at 71.723,69.512 h3
  text "TRACKS : 0.110mm           / GAPS : 0.130mm" at 155.773,67.937 h3
  text "E.   SURFACE FINISH :" at -1.527,66.512 h3
  text "X  ENIG" at 36.973,66.512 h3
  text "IMMERSION SILVER" at 53.473,66.512 h3
  text "IMMERSION TIN" at 87.723,66.512 h3
  text "HASL" at 36.973,63.512 h3
  text "HASL (PB-FREE)" at 53.473,63.512 h3
  text "GOLDEN FINGER" at 87.723,63.512 h3
  text "F.   IMPEDANCE CONTROL :" at -1.527,60.512 h3
  text "NO" at 36.973,60.512 h3
  text "X  YES  (SEE IMPEDANCE TABLE FOR DETAIL INFORMATION)" at 53.473,60.512 h3
  text "G.   THROUGH VIA :" at -1.527,57.512 h3
  text "PLUG THE VIAS WHICH ARE COVERED WITH SOLDERMASK ONE OR TWO SIDE." at 36.973,57.512 h3
  text "PLUG MATERIAL :" at 36.973,54.512 h3
  text "X  SOLDERMASK" at 62.473,54.512 h3
  text "NON-CONDUCTIVE EPOXY." at 87.723,54.512 h3
  text "H.   STACK-UP :" at -1.527,51.512 h3
  text "SEE LAYER STACK-UP SEQUENCE FOR OVERALL THICKNESS." at 36.973,51.512 h3
  text "Layer" at 98.769,38.062 h1.52
  text "Name" at 105.147,38.062 h1.52
  text "Material" at 117.481,38.062 h1.52
  text "Thickness" at 128.564,38.062 h1.52
  text "Constant" at 137.668,38.062 h1.52
  text "Board Layer Stack" at 146.094,38.062 h1.52
  text "Top Overlay" at 105.147,35.014 h1.52
  text "Top Solder" at 105.147,31.966 h1.52
  text "Solder Resist" at 117.481,31.966 h1.52
  text "0,015mm" at 128.564,31.966 h1.52
  text "3,5" at 137.668,31.966 h1.52
  text "1" at 98.769,28.918 h1.52
  text "Top Layer" at 105.147,28.918 h1.52
  text "Copper" at 117.481,28.918 h1.52
  text "0,037mm" at 128.564,28.918 h1.52
  text "Dielectric 2" at 105.147,25.87 h1.52
  text "0,106mm" at 128.564,25.87 h1.52
  text "4,1" at 137.668,25.87 h1.52
  text "2" at 98.768,22.822 h1.52
  text "Signal Layer 1" at 105.147,22.822 h1.52
  text "Copper" at 117.481,22.822 h1.52
  text "0,035mm" at 128.564,22.822 h1.52
  text "Dielectric 1" at 105.147,19.774 h1.52
  text "1,200mm" at 128.564,19.774 h1.52
  text "4,2" at 137.668,19.774 h1.52
  text "3" at 98.769,16.726 h1.52
  text "Signal Layer 2" at 105.147,16.726 h1.52
  text "Copper" at 117.481,16.726 h1.52
  text "0,035mm" at 128.564,16.726 h1.52
  text "Dielectric 3" at 105.147,13.678 h1.52
  text "0,106mm" at 128.564,13.678 h1.52
  text "4,1" at 137.668,13.678 h1.52
  text "4" at 98.769,10.63 h1.52
  text "Bottom Layer" at 105.147,10.63 h1.52
  text "Copper" at 117.481,10.63 h1.52
  text "0,037mm" at 128.564,10.63 h1.52
  text "Bottom Solder" at 105.147,7.582 h1.52
  text "Solder Resist" at 117.481,7.582 h1.52
  text "0,015mm" at 128.564,7.582 h1.52
  text "3,5" at 137.668,7.582 h1.52
  text "Bottom Overlay" at 105.147,4.534 h1.52
  text "Symbol" at 98.79,-2.681 h1.83
  text "Count" at 105.95,-2.681 h1.83
  text "Hole Size" at 113.285,-2.681 h1.83
  text "Plated" at 127.217,-2.681 h1.83
  text "Hole Type" at 133.502,-2.681 h1.83
  text "Drill Layer Pair" at 142.654,-2.681 h1.83
  text "Via/Pad" at 159.997,-2.681 h1.83
  text "Pad Shape" at 167.495,-2.681 h1.83
  text "2" at 105.95,-5.836 h1.52
  text "1,500mm (59,06mil)" at 113.285,-5.836 h1.52
  text "PTH" at 127.217,-5.836 h1.52
  text "Round" at 133.502,-5.836 h1.52
  text "Top Layer - Bottom Layer" at 142.654,-5.836 h1.52
  text "Pad" at 159.997,-5.836 h1.52
  text "Rounded" at 167.495,-5.836 h1.52
  text "2" at 105.95,-8.99 h1.52
  text "1,800mm (70,87mil)" at 113.285,-8.99 h1.52
  text "PTH" at 127.217,-8.99 h1.52
  text "Round" at 133.502,-8.99 h1.52
  text "Top Layer - Bottom Layer" at 142.654,-8.99 h1.52
  text "Pad" at 159.997,-8.99 h1.52
  text "Rounded" at 167.495,-8.99 h1.52
  text "4" at 105.95,-12.144 h1.52
  text "2,200mm (86,61mil)" at 113.285,-12.144 h1.52
  text "PTH" at 127.217,-12.144 h1.52
  text "Round" at 133.502,-12.144 h1.52
  text "Top Layer - Bottom Layer" at 142.654,-12.144 h1.52
  text "Pad" at 159.997,-12.144 h1.52
  text "Rounded" at 167.495,-12.144 h1.52
  text ".Layer_Name" at 4.398,-14.913 h3
  text ".DRL" at 46.093,-14.913 h3
  text "158" at 105.95,-15.298 h1.52
  text "0,300mm (11,81mil)" at 113.285,-15.298 h1.52
  text "PTH" at 127.217,-15.298 h1.52
  text "Round" at 133.502,-15.298 h1.52
  text "Top Layer - Bottom Layer" at 142.654,-15.298 h1.52
  text "Via" at 159.997,-15.298 h1.52
  text "Rounded" at 167.495,-15.298 h1.52
  text "166 Total" at 105.95,-18.452 h1.52
M17-Bottom Courtyard:
  lines w0.01: 50,11.7 50,18.3
M20-Top Title Box:
  circle w0.254: c82.402,-21.633 r1.3
  region: 67.924,-22.726 57.168,-22.726 58.161,-20.234 66.019,-20.234 66.468,-19.474 68.676,-22.023
  region: 81.927,-14.397 66.4,-14.397 65.706,-16.172 64.495,-17.397 63.098,-15.537 63.098,-13.886 64.241,-12.489 65.677,-12.111 81.927,-12.111
  lines w0.254: 58.161,-20.234 66.953,-20.234 63.887,-16.696 cw(c65.691,-14.752) 65.931,-12.111 82.695,-12.111 81.933,-14.397 ; 61.475,-11.864 cw(c63.901,-12.834) 64.138,-10.232 ; 61.514,-11.831 57.168,-22.726 76.49,-22.726 ccw(c76.739,-19.992) 79.288,-21.012 ; 63.254,-15.766 68.676,-22.023 ; 63.508,-15.766 68.813,-21.887 ; 63.508,-15.512 68.813,-21.633 ; 63.606,-14.397 76.599,-14.397 ; 63.635,-15.385 68.94,-21.506 ; 63.762,-15.258 69.067,-21.379 ; 63.889,-15.131 69.194,-21.252 ; 64.016,-15.004 69.321,-21.125 ; 64.071,-13.052 69.376,-19.173 ; 64.139,-10.232 83.589,-10.232 79.289,-21.009 ; 64.143,-14.877 69.393,-20.935 ; 64.143,-14.623 69.448,-20.744 ; 64.143,-14.369 69.448,-20.49 ; 64.143,-13.48 69.448,-19.601 ; 64.27,-14.242 69.575,-20.363 ; 64.27,-13.861 69.575,-19.982 ; 65.642,-20.247 ccw(c65.747,-19.712) 66.044,-19.255 ; 66.728,-14.383 ccw(c66.702,-14.951) 66.372,-15.413 68.737,-18.142 cw(c66.933,-20.085) 67.666,-22.634 ; 73.009,-22.522 75.899,-14.143 ; 73.232,-22.472 76.101,-14.152 ; 73.359,-22.472 76.228,-14.152 ; 73.613,-22.472 76.482,-14.152 ; 73.867,-22.472 76.736,-14.152 ; 74.121,-22.472 76.99,-14.152 ; 74.375,-22.472 77.244,-14.152 ; 74.629,-22.472 77.498,-14.152 ; 74.883,-22.472 77.752,-14.152 ; 75.137,-22.472 78.006,-14.152 ; 75.345,-22.522 78.235,-14.143 ; 78.235,-14.397 81.927,-14.397 ; 81.259,-14.394 82.021,-12.108 ; 81.425,-14.397 82.187,-12.111 ; 81.679,-14.397 82.441,-12.111
  lines w0.3: -4.602,-21.613 55.398,-21.613 ; -4.602,-16.613 55.398,-16.613 ; -4.602,-11.613 55.398,-11.613 ; 35.398,-26.613 35.398,-11.613 ; 55.398,-26.613 55.398,-6.613 ; 73.009,-22.522 75.345,-22.522 ; -4.602,-26.613 85.398,-26.613 85.398,-6.613 -4.602,-6.613 -4.602,-26.613
  text "Project: '.Board_Name'" at -3.602,-9.829 h3
  text "Layer:" at -3.602,-14.913 h3
  text "Gerber:" at 36.387,-14.913 h3
  text "Variant: '.VariantName'" at -3.602,-19.913 h3
  text "Ref: MB1854" at 36.514,-19.913 h3
  text "R" at 81.894,-22.395 h1.52
  text "Date: 22-09-28" at -3.602,-24.913 h3
  text "Rev: '.Board_PCB_Revision'" at 36.457,-24.913 h3
M21-Bottom Title Box:
  circle w0.254: c-1.427,-21.625 r1.3
  region: -0.952,-14.389 14.575,-14.389 15.27,-16.164 16.48,-17.389 17.877,-15.529 17.877,-13.878 16.734,-12.481 15.298,-12.103 -0.952,-12.103
  region: 13.051,-22.718 23.807,-22.718 22.814,-20.226 14.956,-20.226 14.508,-19.466 12.299,-22.015
  lines w0.254: -1.466,-12.103 -0.704,-14.389 ; -1.212,-12.103 -0.45,-14.389 ; -1.046,-12.1 -0.284,-14.386 ; -0.958,-14.389 -1.72,-12.103 15.044,-12.103 cw(c15.284,-14.744) 17.088,-16.688 14.022,-20.226 22.814,-20.226 ; -0.952,-14.389 2.741,-14.389 ; 1.687,-21.004 ccw(c4.236,-19.984) 4.485,-22.718 23.807,-22.718 19.461,-11.823 ; 1.686,-21.001 -2.613,-10.224 16.836,-10.224 ; 2.741,-14.135 5.63,-22.514 ; 2.969,-14.144 5.838,-22.464 ; 3.223,-14.144 6.092,-22.464 ; 3.477,-14.144 6.346,-22.464 ; 3.731,-14.144 6.6,-22.464 ; 3.985,-14.144 6.854,-22.464 ; 4.239,-14.144 7.108,-22.464 ; 4.376,-14.389 17.369,-14.389 ; 4.493,-14.144 7.362,-22.464 ; 4.747,-14.144 7.616,-22.464 ; 4.874,-14.144 7.743,-22.464 ; 5.076,-14.135 7.966,-22.514 ; 11.4,-20.355 16.705,-14.234 ; 11.4,-19.974 16.705,-13.853 ; 11.527,-20.736 16.832,-14.615 ; 11.527,-20.482 16.832,-14.361 ; 11.527,-19.593 16.832,-13.472 ; 11.582,-20.927 16.832,-14.869 ; 11.6,-19.165 16.905,-13.044 ; 11.654,-21.117 16.959,-14.996 ; 11.781,-21.244 17.086,-15.123 ; 11.908,-21.371 17.213,-15.25 ; 12.035,-21.498 17.34,-15.377 ; 12.162,-21.879 17.467,-15.758 ; 12.162,-21.625 17.467,-15.504 ; 12.299,-22.015 17.721,-15.758 ; 13.31,-22.626 cw(c14.042,-20.077) 12.239,-18.134 14.603,-15.405 ccw(c14.273,-14.943) 14.247,-14.375 ; 14.931,-19.247 ccw(c15.229,-19.704) 15.334,-20.239 ; 16.838,-10.224 cw(c17.074,-12.826) 19.5,-11.856
  lines w0.3: 5.63,-22.514 7.966,-22.514 ; 25.391,-26.605 25.391,-6.605 ; 25.391,-21.605 85.391,-21.605 ; 25.391,-16.605 85.391,-16.605 ; 25.391,-11.605 85.391,-11.605 ; 45.391,-26.605 45.391,-11.605 ; -4.609,-26.605 -4.609,-6.605 85.391,-6.605 85.391,-26.605 -4.609,-26.605
  text "Project: '.Board_Name'" at 84.197,-9.821 h3
  text "Gerber:" at 44.208,-14.905 h3
  text "Layer:" at 84.196,-14.905 h3
  text "Ref: MB1854" at 44.208,-19.905 h3
  text "Variant: '.VariantName'" at 84.197,-19.905 h3
  text "R" at -0.919,-22.387 h1.52
  text "Rev: '.Board_PCB_Revision'" at 44.265,-24.905 h3
  text "Date: 22-09-28" at 84.197,-24.905 h3

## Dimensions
0.003,-0.15 to 50.003,20.95 on M2-Board Dimensions
2,30 to 2,0 on M2-Board Dimensions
